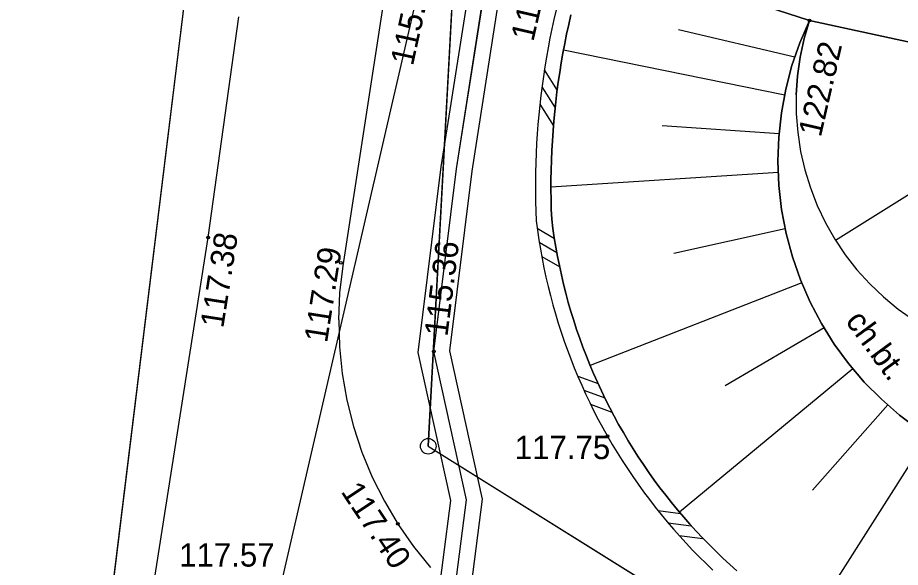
# Model space of a CAD drawing. Extents: x 6424617 to 6425697, y 5665845 to 5667190.
# Drawn here: x 6425187.36 to 6425215.73, y 5665976.7 to 5665994.36 of the extents above; entities that cross this region are included whole.
import ezdxf

# ---------------------------------------------------------------- set-up
doc = ezdxf.new("R2010")
doc.units = 0
for name, color, linetype in [('Warstwa 1', 7, 'Continuous'), ('Warstwa 10', 7, 'Continuous'), ('Warstwa 12', 7, 'Continuous'), ('Warstwa 14', 7, 'Continuous'), ('Warstwa 15', 7, 'Continuous'), ('Warstwa 20', 7, 'Continuous'), ('Warstwa 21', 7, 'Continuous'), ('Warstwa 25', 7, 'Continuous'), ('Warstwa 6', 7, 'Continuous'), ('Warstwa 61', 7, 'Continuous'), ('Warstwa 8', 7, 'Continuous'), ('Warstwa 9', 7, 'Continuous')]:
    doc.layers.add(name, color=color, linetype=linetype)

msp = doc.modelspace()

# ---------------------------------------------------------------- linework, layer by layer
at = {"layer": 'Warstwa 1'}
for p, q in [((6425188.723, 5665962.219), (6425193.713, 5666002.874)), ((6425188.723, 5665962.219), (6425193.713, 5666002.874)), ((6425200.56, 5665980.59), (6425201.44, 5665996.89)), ((6425200.56, 5665980.59), (6425201.44, 5665996.89)), ((6425200.56, 5665980.59), (6425215.3, 5665971.39)), ((6425200.56, 5665980.59), (6425215.3, 5665971.39))]:
    msp.add_line(p, q, dxfattribs=at)
at = {"layer": 'Warstwa 10'}
for p, q in [((6425204.29, 5665992.679), (6425204.702, 5665992.021)), ((6425204.213, 5665992.136), (6425204.636, 5665991.461)), ((6425204.146, 5665991.576), (6425204.582, 5665990.88)), ((6425204.061, 5665987.592), (6425204.613, 5665987.269)), ((6425204.127, 5665987.144), (6425204.692, 5665986.812)), ((6425204.206, 5665986.689), (6425204.783, 5665986.349)), ((6425205.365, 5665982.838), (6425206.016, 5665982.602)), ((6425205.563, 5665982.39), (6425206.23, 5665982.15)), ((6425205.777, 5665981.937), (6425206.464, 5665981.69)), ((6425207.945, 5665978.521), (6425208.665, 5665978.433)), ((6425208.271, 5665978.125), (6425209.014, 5665978.034)), ((6425208.618, 5665977.726), (6425209.387, 5665977.632))]:
    msp.add_line(p, q, dxfattribs=at)
for points in [[(6425195.083, 5665928.73), (6425195.5, 5665933.49), (6425198.27, 5665958.16), (6425199.83, 5665967.3), (6425201.04, 5665973.05), (6425201.79, 5665978.87), (6425200.74, 5665983.63), (6425201.47, 5665989.5), (6425203.65, 5666003.34), (6425207.21, 5666026.39)], [(6425204.667, 5665994.606), (6425204.597, 5665994.304), (6425204.531, 5665994.001), (6425204.469, 5665993.697), (6425204.411, 5665993.392), (6425204.356, 5665993.086), (6425204.306, 5665992.78), (6425204.259, 5665992.473), (6425204.216, 5665992.166), (6425204.177, 5665991.858), (6425204.143, 5665991.549), (6425204.112, 5665991.24), (6425204.085, 5665990.931), (6425204.061, 5665990.622), (6425204.042, 5665990.312), (6425204.027, 5665990.002), (6425204.016, 5665989.692), (6425204.008, 5665989.381), (6425204.005, 5665989.071), (6425204.005, 5665988.761), (6425204.01, 5665988.45), (6425204.018, 5665988.14), (6425204.03, 5665987.83), (6425204.07, 5665987.527), (6425204.114, 5665987.225), (6425204.163, 5665986.923), (6425204.218, 5665986.622), (6425204.277, 5665986.323), (6425204.341, 5665986.024), (6425204.41, 5665985.727), (6425204.484, 5665985.43), (6425204.563, 5665985.135), (6425204.647, 5665984.841), (6425204.736, 5665984.549), (6425204.829, 5665984.258), (6425204.928, 5665983.969), (6425205.031, 5665983.681), (6425205.139, 5665983.395), (6425205.251, 5665983.111), (6425205.369, 5665982.829), (6425205.49, 5665982.549), (6425205.617, 5665982.271), (6425205.748, 5665981.995), (6425205.884, 5665981.722), (6425206.024, 5665981.45), (6425206.169, 5665981.181), (6425206.318, 5665980.914), (6425206.471, 5665980.65), (6425206.629, 5665980.389), (6425206.791, 5665980.13), (6425206.958, 5665979.874), (6425207.129, 5665979.62), (6425207.303, 5665979.37), (6425207.482, 5665979.122), (6425207.665, 5665978.878), (6425207.852, 5665978.636), (6425208.043, 5665978.398), (6425208.238, 5665978.162), (6425208.437, 5665977.93), (6425208.64, 5665977.702), (6425208.846, 5665977.477), (6425209.056, 5665977.255), (6425209.27, 5665977.037), (6425209.488, 5665976.822), (6425209.708, 5665976.611)], [(6425210.476, 5665976.588), (6425210.25, 5665976.79), (6425210.027, 5665976.997), (6425209.808, 5665977.207), (6425209.593, 5665977.421), (6425209.381, 5665977.639), (6425209.173, 5665977.86), (6425208.968, 5665978.084), (6425208.768, 5665978.312), (6425208.571, 5665978.544), (6425208.378, 5665978.778), (6425208.19, 5665979.016), (6425208.005, 5665979.257), (6425207.824, 5665979.502), (6425207.648, 5665979.749), (6425207.476, 5665979.999), (6425207.308, 5665980.252), (6425207.144, 5665980.508), (6425206.985, 5665980.766), (6425206.83, 5665981.028), (6425206.679, 5665981.291), (6425206.533, 5665981.558), (6425206.392, 5665981.826), (6425206.255, 5665982.097), (6425206.123, 5665982.371), (6425205.995, 5665982.646), (6425205.872, 5665982.924), (6425205.754, 5665983.204), (6425205.64, 5665983.486), (6425205.532, 5665983.769), (6425205.428, 5665984.054), (6425205.329, 5665984.342), (6425205.235, 5665984.63), (6425205.145, 5665984.92), (6425205.061, 5665985.212), (6425204.982, 5665985.505), (6425204.907, 5665985.8), (6425204.838, 5665986.095), (6425204.773, 5665986.392), (6425204.714, 5665986.69), (6425204.659, 5665986.989), (6425204.61, 5665987.288), (6425204.566, 5665987.589), (6425204.527, 5665987.89), (6425204.515, 5665988.204), (6425204.507, 5665988.519), (6425204.504, 5665988.833), (6425204.504, 5665989.148), (6425204.509, 5665989.463), (6425204.518, 5665989.777), (6425204.531, 5665990.091), (6425204.548, 5665990.405), (6425204.569, 5665990.719), (6425204.595, 5665991.033), (6425204.624, 5665991.346), (6425204.657, 5665991.659), (6425204.695, 5665991.971), (6425204.737, 5665992.283), (6425204.783, 5665992.594), (6425204.833, 5665992.905), (6425204.887, 5665993.215), (6425204.945, 5665993.524), (6425205.007, 5665993.832), (6425205.073, 5665994.14), (6425205.143, 5665994.446)]]:
    msp.add_lwpolyline(points, dxfattribs=at)
msp.add_circle((6425200.56, 5665980.59), 0.25, dxfattribs=at)
at = {"layer": 'Warstwa 12'}
msp.add_lwpolyline([(6425072.972, 5666031.235), (6425127.389, 5666016.189), (6425160.219, 5666007.031), (6425200.399, 5665995.948), (6425194.084, 5665968.641), (6425195.818, 5665968.224), (6425197.014, 5665967.931), (6425198.547, 5665967.517), (6425202.73, 5665966.36), (6425217.62, 5665962.23), (6425252.45, 5665952.66), (6425263.6, 5665949.51), (6425264.12, 5665949.09), (6425266.08, 5665945.84), (6425266.65, 5665945.4), (6425269.78, 5665944.54), (6425271.04, 5665944.25), (6425271.66, 5665944.09)], dxfattribs=at)
at = {"layer": 'Warstwa 14'}
msp.add_circle((6425200.74, 5665983.63), 0.045, dxfattribs=at)
at = {"layer": 'Warstwa 20'}
msp.add_lwpolyline([(6425212.81, 5665994.27), (6425212.503, 5665993.554), (6425212.249, 5665992.817), (6425212.051, 5665992.063), (6425211.91, 5665991.297), (6425211.825, 5665990.523), (6425211.798, 5665989.744), (6425211.829, 5665988.965), (6425211.917, 5665988.191), (6425212.063, 5665987.426), (6425212.264, 5665986.673), (6425212.521, 5665985.938), (6425212.831, 5665985.223), (6425213.194, 5665984.533), (6425213.606, 5665983.873), (6425214.067, 5665983.244), (6425214.573, 5665982.651), (6425215.121, 5665982.098), (6425215.708, 5665981.586), (6425216.332, 5665981.119)], dxfattribs=at)
at = {"layer": 'Warstwa 21'}
for points in [[(6425210.476, 5665976.588), (6425210.25, 5665976.79), (6425210.027, 5665976.997), (6425209.808, 5665977.207), (6425209.593, 5665977.421), (6425209.381, 5665977.639), (6425209.173, 5665977.86), (6425208.968, 5665978.084), (6425208.768, 5665978.312), (6425208.571, 5665978.544), (6425208.378, 5665978.778), (6425208.19, 5665979.016), (6425208.005, 5665979.257), (6425207.824, 5665979.502), (6425207.648, 5665979.749), (6425207.476, 5665979.999), (6425207.308, 5665980.252), (6425207.144, 5665980.508), (6425206.985, 5665980.766), (6425206.83, 5665981.028), (6425206.679, 5665981.291), (6425206.533, 5665981.558), (6425206.392, 5665981.826), (6425206.255, 5665982.097), (6425206.123, 5665982.371), (6425205.995, 5665982.646), (6425205.872, 5665982.924), (6425205.754, 5665983.204), (6425205.64, 5665983.486), (6425205.532, 5665983.769), (6425205.428, 5665984.054), (6425205.329, 5665984.342), (6425205.235, 5665984.63), (6425205.145, 5665984.92), (6425205.061, 5665985.212), (6425204.982, 5665985.505), (6425204.907, 5665985.8), (6425204.838, 5665986.095), (6425204.773, 5665986.392), (6425204.714, 5665986.69), (6425204.659, 5665986.989), (6425204.61, 5665987.288), (6425204.566, 5665987.589), (6425204.527, 5665987.89), (6425204.515, 5665988.204), (6425204.507, 5665988.519), (6425204.504, 5665988.833), (6425204.504, 5665989.148), (6425204.509, 5665989.463), (6425204.518, 5665989.777), (6425204.531, 5665990.091), (6425204.548, 5665990.405), (6425204.569, 5665990.719), (6425204.595, 5665991.033), (6425204.624, 5665991.346), (6425204.657, 5665991.659), (6425204.695, 5665991.971), (6425204.737, 5665992.283), (6425204.783, 5665992.594), (6425204.833, 5665992.905), (6425204.887, 5665993.215), (6425204.945, 5665993.524), (6425205.007, 5665993.832), (6425205.073, 5665994.14), (6425205.143, 5665994.446)], [(6425212.81, 5665994.27), (6425212.637, 5665993.686), (6425212.508, 5665993.091), (6425212.423, 5665992.489), (6425212.382, 5665991.881), (6425212.385, 5665991.272), (6425212.433, 5665990.665), (6425212.525, 5665990.063), (6425212.661, 5665989.47), (6425212.84, 5665988.888), (6425213.061, 5665988.32), (6425213.323, 5665987.771), (6425213.624, 5665987.242), (6425213.963, 5665986.736), (6425214.338, 5665986.256), (6425214.747, 5665985.805), (6425215.188, 5665985.385), (6425215.659, 5665984.999), (6425216.156, 5665984.648)]]:
    msp.add_lwpolyline(points, dxfattribs=at)
at = {"layer": 'Warstwa 25'}
for centre in [(6425212.81, 5665994.27), (6425193.486, 5665987.3), (6425197.752, 5665986.483), (6425206.32, 5665980.91), (6425199.581, 5665978.097)]:
    msp.add_circle(centre, 0.045, dxfattribs=at)
at = {"layer": 'Warstwa 6'}
for points in [[(6425242.84, 5666212.49), (6425237.49, 5666195.18), (6425235.64, 5666175.69), (6425221.4, 5666109.24), (6425216.06, 5666092.43), (6425215.14, 5666072.15), (6425206.5, 5666014.74), (6425201.44, 5665996.89), (6425200.56, 5665980.59), (6425215.3, 5665971.39), (6425213.05, 5665952.08), (6425191.264, 5665958.118), (6425188.723, 5665962.219), (6425193.713, 5666002.874), (6425197.98, 5666033.305), (6425201.568, 5666056.314), (6425211.111, 5666112.114), (6425211.695, 5666114.967), (6425227.334, 5666191.99), (6425232.133, 5666212.582)], [(6425242.84, 5666212.49), (6425237.49, 5666195.18), (6425235.64, 5666175.69), (6425221.4, 5666109.24), (6425216.06, 5666092.43), (6425215.14, 5666072.15), (6425206.5, 5666014.74), (6425201.44, 5665996.89), (6425200.56, 5665980.59), (6425215.3, 5665971.39), (6425213.05, 5665952.08), (6425244.899, 5665943.26), (6425246.948, 5665948.976), (6425255.27, 5665979.789), (6425282.481, 5666076.105), (6425288.966, 5666103.799), (6425290.169, 5666109.024), (6425305.245, 5666173.41), (6425312.278, 5666201.804)]]:
    msp.add_lwpolyline(points, dxfattribs=at)
msp.add_lwpolyline([(6425193.713, 5666002.874), (6425197.98, 5666033.305), (6425201.568, 5666056.314), (6425175.276, 5665962.552), (6425191.264, 5665958.118), (6425188.723, 5665962.219)], close=True, dxfattribs=at)
at = {"layer": 'Warstwa 61'}
msp.add_lwpolyline([(6425195.083, 5665928.73), (6425195.5, 5665933.49), (6425198.27, 5665958.16), (6425199.83, 5665967.3), (6425201.04, 5665973.05), (6425201.79, 5665978.87), (6425200.74, 5665983.63), (6425201.47, 5665989.5), (6425207.21, 5666026.39), (6425209.71, 5666040.77), (6425212.26, 5666054.53), (6425214.289, 5666065.784)], dxfattribs=at)
at = {"layer": 'Warstwa 8'}
for p, q in [((6425197.82, 5665986.381), (6425202, 5666013.465)), ((6425193.486, 5665987.3), (6425194.474, 5665994.385)), ((6425191.19, 5665972.647), (6425193.486, 5665987.3)), ((6425197.72, 5665985.52), (6425197.82, 5665986.381)), ((6425197.682, 5665984.653), (6425197.72, 5665985.52)), ((6425197.682, 5665984.653), (6425197.707, 5665983.786)), ((6425197.707, 5665983.786), (6425197.795, 5665982.923)), ((6425197.795, 5665982.923), (6425197.946, 5665982.069)), ((6425197.946, 5665982.069), (6425198.157, 5665981.228)), ((6425198.157, 5665981.228), (6425198.429, 5665980.404)), ((6425198.429, 5665980.404), (6425198.76, 5665979.602)), ((6425198.76, 5665979.602), (6425199.149, 5665978.826)), ((6425199.149, 5665978.826), (6425199.592, 5665978.081)), ((6425199.592, 5665978.081), (6425200.088, 5665977.369)), ((6425200.088, 5665977.369), (6425200.635, 5665976.696))]:
    msp.add_line(p, q, dxfattribs=at)
for points in [[(6425194.59, 5665928.841), (6425195.002, 5665933.54), (6425197.775, 5665958.23), (6425199.339, 5665967.394), (6425200.547, 5665973.134), (6425201.283, 5665978.847), (6425200.233, 5665983.606), (6425200.975, 5665989.57), (6425203.156, 5666003.417), (6425206.716, 5666026.466), (6425209.218, 5666040.858), (6425211.768, 5666054.62), (6425213.782, 5666065.79)], [(6425214.796, 5666065.778), (6425212.752, 5666054.44), (6425210.202, 5666040.682), (6425207.704, 5666026.314), (6425201.965, 5665989.43), (6425201.247, 5665983.654), (6425202.297, 5665978.893), (6425201.533, 5665972.966), (6425200.321, 5665967.206), (6425198.765, 5665958.09), (6425195.998, 5665933.44), (6425195.575, 5665928.62)]]:
    msp.add_lwpolyline(points, dxfattribs=at)
at = {"layer": 'Warstwa 9'}
for p, q in [((6425212.503, 5665993.554), (6425212.81, 5665994.27)), ((6425212.637, 5665993.686), (6425212.81, 5665994.27)), ((6425212.341, 5665993.085), (6425208.6, 5665993.967)), ((6425212.249, 5665992.817), (6425212.503, 5665993.554)), ((6425212.508, 5665993.091), (6425212.637, 5665993.686)), ((6425212.014, 5665991.864), (6425204.906, 5665993.319)), ((6425212.423, 5665992.489), (6425212.508, 5665993.091)), ((6425212.051, 5665992.063), (6425212.249, 5665992.817)), ((6425212.382, 5665991.881), (6425212.423, 5665992.489)), ((6425211.91, 5665991.297), (6425212.051, 5665992.063)), ((6425212.382, 5665991.881), (6425212.385, 5665991.272)), ((6425220.85, 5665991.71), (6425213.652, 5665987.201)), ((6425211.825, 5665990.523), (6425211.91, 5665991.297)), ((6425212.385, 5665991.272), (6425212.433, 5665990.665)), ((6425211.837, 5665990.629), (6425208.081, 5665990.887)), ((6425211.798, 5665989.744), (6425211.825, 5665990.523)), ((6425212.433, 5665990.665), (6425212.525, 5665990.063)), ((6425212.525, 5665990.063), (6425212.661, 5665989.47)), ((6425211.798, 5665989.744), (6425211.829, 5665988.965)), ((6425211.812, 5665989.383), (6425204.504, 5665988.913)), ((6425212.661, 5665989.47), (6425212.84, 5665988.888)), ((6425211.829, 5665988.965), (6425211.917, 5665988.191)), ((6425212.84, 5665988.888), (6425213.061, 5665988.32)), ((6425211.917, 5665988.191), (6425212.063, 5665987.426)), ((6425213.061, 5665988.32), (6425213.323, 5665987.771)), ((6425212.034, 5665987.579), (6425208.455, 5665986.786)), ((6425213.323, 5665987.771), (6425213.624, 5665987.242)), ((6425212.063, 5665987.426), (6425212.264, 5665986.673)), ((6425213.624, 5665987.242), (6425213.963, 5665986.736)), ((6425213.963, 5665986.736), (6425214.338, 5665986.256)), ((6425212.264, 5665986.673), (6425212.521, 5665985.938)), ((6425214.338, 5665986.256), (6425214.747, 5665985.805)), ((6425212.521, 5665985.938), (6425212.831, 5665985.223)), ((6425212.563, 5665985.841), (6425205.763, 5665983.182)), ((6425214.747, 5665985.805), (6425215.188, 5665985.385)), ((6425215.188, 5665985.385), (6425215.659, 5665984.999)), ((6425212.831, 5665985.223), (6425213.194, 5665984.533)), ((6425215.659, 5665984.999), (6425216.156, 5665984.648)), ((6425213.194, 5665984.533), (6425213.606, 5665983.873)), ((6425213.279, 5665984.396), (6425210.104, 5665982.53)), ((6425213.606, 5665983.873), (6425214.067, 5665983.244)), ((6425214.209, 5665983.077), (6425208.633, 5665978.471)), ((6425214.067, 5665983.244), (6425214.573, 5665982.651)), ((6425214.573, 5665982.651), (6425215.121, 5665982.098)), ((6425215.33, 5665981.916), (6425212.907, 5665979.176)), ((6425215.121, 5665982.098), (6425215.708, 5665981.586)), ((6425215.708, 5665981.586), (6425216.332, 5665981.119)), ((6425216.615, 5665980.938), (6425212.801, 5665974.933))]:
    msp.add_line(p, q, dxfattribs=at)
msp.add_lwpolyline([(6425203.905, 5665997.065), (6425205.262, 5665996.695), (6425205.746, 5665996.563), (6425212.81, 5665994.27), (6425219.483, 5665992.823), (6425224.359, 5666011.311), (6425224.664, 5666013.286), (6425232.731, 5666065.562), (6425217.263, 5666065.748), (6425213.633, 5666043.855), (6425209.646, 5666017.528), (6425208.952, 5666013.449), (6425207.808, 5666009.369)], close=True, dxfattribs=at)
for points in [[(6425216.332, 5665981.119), (6425215.708, 5665981.586), (6425215.121, 5665982.098), (6425214.573, 5665982.651), (6425214.067, 5665983.244), (6425213.606, 5665983.873), (6425213.194, 5665984.533), (6425212.831, 5665985.223), (6425212.521, 5665985.938), (6425212.264, 5665986.673), (6425212.063, 5665987.426), (6425211.917, 5665988.191), (6425211.829, 5665988.965), (6425211.798, 5665989.744), (6425211.825, 5665990.523), (6425211.91, 5665991.297), (6425212.051, 5665992.063), (6425212.249, 5665992.817), (6425212.503, 5665993.554), (6425212.81, 5665994.27), (6425205.746, 5665996.563)], [(6425205.143, 5665994.446), (6425205.073, 5665994.14), (6425205.007, 5665993.832), (6425204.945, 5665993.524), (6425204.887, 5665993.215), (6425204.833, 5665992.905), (6425204.783, 5665992.594), (6425204.737, 5665992.283), (6425204.695, 5665991.971), (6425204.657, 5665991.659), (6425204.624, 5665991.346), (6425204.595, 5665991.033), (6425204.569, 5665990.719), (6425204.548, 5665990.405), (6425204.531, 5665990.091), (6425204.518, 5665989.777), (6425204.509, 5665989.463), (6425204.504, 5665989.148), (6425204.504, 5665988.833), (6425204.507, 5665988.519), (6425204.515, 5665988.204), (6425204.527, 5665987.89), (6425204.566, 5665987.589), (6425204.61, 5665987.288), (6425204.659, 5665986.989), (6425204.714, 5665986.69), (6425204.773, 5665986.392), (6425204.838, 5665986.095), (6425204.907, 5665985.8), (6425204.982, 5665985.505), (6425205.061, 5665985.212), (6425205.145, 5665984.92), (6425205.235, 5665984.63), (6425205.329, 5665984.342), (6425205.428, 5665984.054), (6425205.532, 5665983.769), (6425205.64, 5665983.486), (6425205.754, 5665983.204), (6425205.872, 5665982.924), (6425205.995, 5665982.646), (6425206.123, 5665982.371), (6425206.255, 5665982.097), (6425206.392, 5665981.826), (6425206.533, 5665981.558), (6425206.679, 5665981.291), (6425206.83, 5665981.028), (6425206.985, 5665980.766), (6425207.144, 5665980.508), (6425207.308, 5665980.252), (6425207.476, 5665979.999), (6425207.648, 5665979.749), (6425207.824, 5665979.502), (6425208.005, 5665979.257), (6425208.19, 5665979.016), (6425208.378, 5665978.778), (6425208.571, 5665978.544), (6425208.768, 5665978.312), (6425208.968, 5665978.084), (6425209.173, 5665977.86), (6425209.381, 5665977.639), (6425209.593, 5665977.421), (6425209.808, 5665977.207), (6425210.027, 5665976.997), (6425210.25, 5665976.79), (6425210.476, 5665976.588)], [(6425219.483, 5665992.823), (6425212.81, 5665994.27), (6425212.637, 5665993.686), (6425212.508, 5665993.091), (6425212.423, 5665992.489), (6425212.382, 5665991.881), (6425212.385, 5665991.272), (6425212.433, 5665990.665), (6425212.525, 5665990.063), (6425212.661, 5665989.47), (6425212.84, 5665988.888), (6425213.061, 5665988.32), (6425213.323, 5665987.771), (6425213.624, 5665987.242), (6425213.963, 5665986.736), (6425214.338, 5665986.256), (6425214.747, 5665985.805), (6425215.188, 5665985.385), (6425215.659, 5665984.999), (6425216.156, 5665984.648)]]:
    msp.add_lwpolyline(points, dxfattribs=at)

# ---------------------------------------------------------------- texts
at = {"layer": 'Warstwa 14'}
for s, rotation, p in [('115.47', 77.6702, (6425200.067, 5665992.786)), ('115.36', 82.9127, (6425201.175, 5665984.092))]:
    msp.add_text(s, height=0.75, rotation=rotation, dxfattribs=at).set_placement(p)
at = {"layer": 'Warstwa 15'}
msp.add_text('117.57', height=0.75, dxfattribs=at).set_placement((6425192.554, 5665976.724))
at = {"layer": 'Warstwa 25'}
for s, rotation, p in [('117.65', 76.9769, (6425203.935, 5665993.565)), ('122.82', 76.9769, (6425213.175, 5665990.494)), ('117.38', 81.0964, (6425193.971, 5665984.363)), ('117.29', 81.0964, (6425197.307, 5665983.89)), ('117.40', 303.5301, (6425197.732, 5665979.133))]:
    msp.add_text(s, height=0.75, rotation=rotation, dxfattribs=at).set_placement(p)
msp.add_text('117.75', height=0.75, dxfattribs=at).set_placement((6425203.34, 5665980.178))
at = {"layer": 'Warstwa 9'}
msp.add_text('ch.bt.', height=0.75, rotation=306.223, dxfattribs=at).set_placement((6425213.942, 5665984.608))

doc.saveas('drawing.dxf')
